// Mitsubishi GX Works2 project: MM-17MR-4MTS-F350-H3G-B例程   PLC: FX3G

PROGRAM MAIN
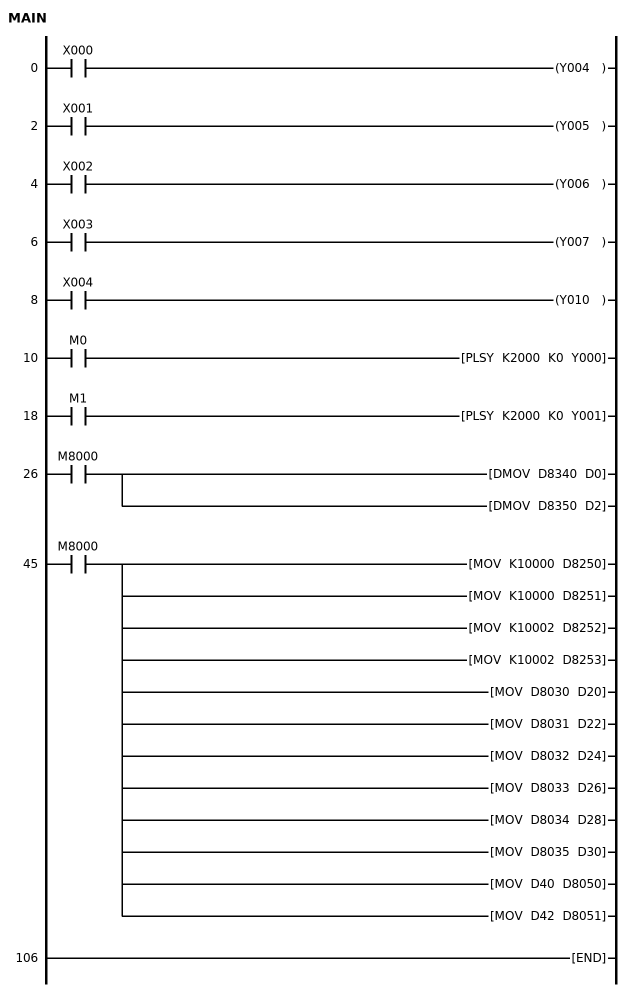
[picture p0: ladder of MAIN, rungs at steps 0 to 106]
0     LD      X000
      OUT     Y004
2     LD      X001
      OUT     Y005
4     LD      X002
      OUT     Y006
6     LD      X003
      OUT     Y007
8     LD      X004
      OUT     Y010
10    LD      M0
      PLSY    K2000 K0 Y000
18    LD      M1
      PLSY    K2000 K0 Y001
26    LD      M8000
      DMOV    D8340 D0
      DMOV    D8350 D2
45    LD      M8000
      MOV     K10000 D8250
      MOV     K10000 D8251
      MOV     K10002 D8252
      MOV     K10002 D8253
      MOV     D8030 D20
      MOV     D8031 D22
      MOV     D8032 D24
      MOV     D8033 D26
      MOV     D8034 D28
      MOV     D8035 D30
      MOV     D40 D8050
      MOV     D42 D8051
106   END
END_PROGRAM
